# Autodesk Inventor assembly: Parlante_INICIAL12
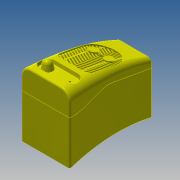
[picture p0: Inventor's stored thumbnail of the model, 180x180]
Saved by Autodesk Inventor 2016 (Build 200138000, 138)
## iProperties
Created: 2013-03
Part Number: Parlante_INICIAL12
Document SubType Name: Assembly
Designer: julian.chica
Author: julian.chica
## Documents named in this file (4)
- C:\Test ExamProfessor 2015\Parlante_INICIAL12.iam
- C:\Test ExamProfessor 2015\frontal.ipt
- C:\Test ExamProfessor 2015\trasero.ipt
- C:\Test ExamProfessor 2015\Perilla.ipt
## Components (3 placed, 3 different names)
1. frontal:1
2. trasero:1
3. Perilla:1
